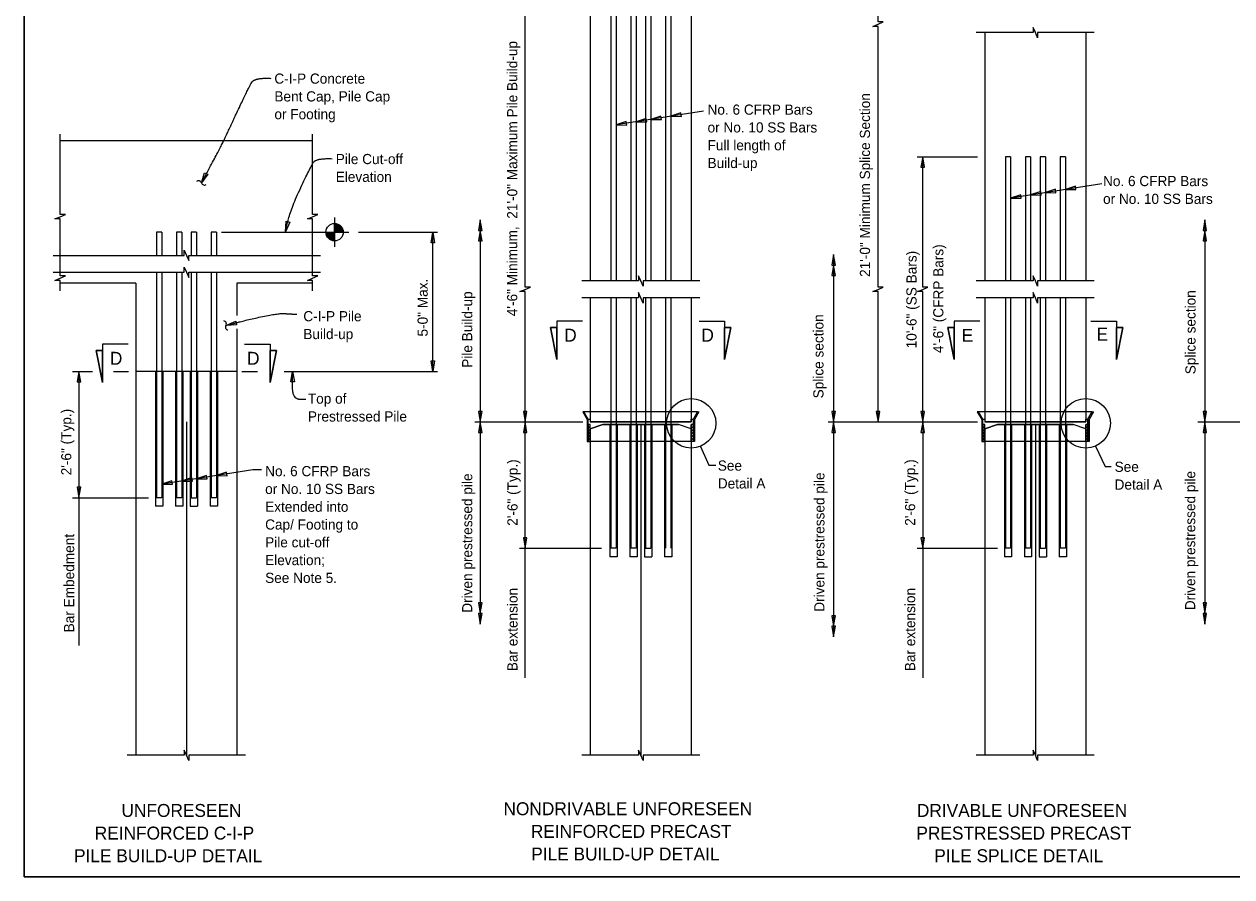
# Model space of a CAD drawing. Extents: x 0 to 41.1, y 0 to 25.9.
# Drawn here: x 0 to 23.92, y 0 to 16.88 of the extents above; entities that cross this region are included whole.
import ezdxf

# ---------------------------------------------------------------- set-up
doc = ezdxf.new("R2010")
doc.units = 0
for name, color, linetype in [('CL_Minor', 7, 'Continuous'), ('Dimension', 7, 'Continuous'), ('Miscellaneous', 7, 'Continuous'), ('Miscellaneous1', 7, 'Continuous'), ('PileConc', 7, 'Continuous'), ('PileConc_h', 7, 'Continuous'), ('Rebar', 7, 'Continuous'), ('Rebar_h', 7, 'Continuous'), ('SteelGirder', 7, 'Continuous'), ('SteelGirder_h', 7, 'Continuous'), ('Symbols', 7, 'Continuous'), ('TextStructures', 7, 'Continuous')]:
    doc.layers.add(name, color=color, linetype=linetype)

msp = doc.modelspace()

# ---------------------------------------------------------------- linework, layer by layer
at = {"layer": 'CL_Minor'}
for p, q in [((3.214, 9.004), (3.214, 2.407)), ((12.212, 8.942), (12.212, 2.407)), ((20.027, 8.942), (20.027, 2.407))]:
    msp.add_line(p, q, dxfattribs=at)
at = {"layer": 'Dimension'}
for p, q in [((13.454, 15.159), (11.723, 14.886)), ((17.687, 14.254), (18.882, 14.254)), ((21.342, 13.72), (19.538, 13.435)), ((6.148, 13.051), (6.148, 12.472)), ((9.033, 13.005), (9.033, 9.005)), ((23.383, 13.005), (23.383, 9.004)), ((3.908, 12.762), (6.432, 12.762)), ((6.619, 12.762), (8.188, 12.762)), ((8.094, 10.004), (8.094, 12.762)), ((16.031, 12.319), (16.031, 9.004)), ((10.553, 10.243), (10.426, 10.876)), ((10.426, 10.876), (10.553, 10.876)), ((11.059, 11.002), (10.553, 11.002)), ((10.553, 11.002), (10.553, 10.243)), ((13.366, 11.002), (13.872, 11.002)), ((13.872, 11.002), (13.872, 10.243)), ((13.872, 10.243), (13.998, 10.876)), ((13.998, 10.876), (13.872, 10.876)), ((18.422, 10.239), (18.295, 10.872)), ((18.295, 10.872), (18.422, 10.872)), ((18.928, 10.999), (18.422, 10.999)), ((18.422, 10.999), (18.422, 10.239)), ((21.127, 10.999), (21.633, 10.999)), ((21.633, 10.999), (21.633, 10.239)), ((21.633, 10.239), (21.759, 10.872)), ((21.759, 10.872), (21.633, 10.872)), ((2.06, 10.544), (1.554, 10.544)), ((1.554, 10.544), (1.554, 9.785)), ((4.367, 10.544), (4.873, 10.544)), ((4.873, 10.544), (4.873, 9.785)), ((1.554, 9.785), (1.428, 10.417)), ((1.428, 10.417), (1.554, 10.417)), ((4.873, 9.785), (5, 10.417)), ((5, 10.417), (4.873, 10.417)), ((0.96, 10.004), (1.351, 10.004)), ((1.085, 10.004), (1.085, 7.504)), ((1.77, 10.004), (2.068, 10.004)), ((4.314, 10.004), (4.619, 10.004)), ((5.149, 10.004), (8.188, 10.004)), ((8.923, 9.004), (11.067, 9.004)), ((9.033, 9.005), (9.033, 5.004)), ((15.921, 9.004), (18.882, 9.004)), ((16.031, 9.004), (16.031, 4.754)), ((17.797, 9.004), (17.797, 6.504)), ((23.246, 9.004), (26.46, 9.004)), ((23.383, 9.004), (23.383, 5.004)), ((13.394, 8.517), (13.56, 8.15)), ((21.216, 8.525), (21.408, 8.124)), ((13.56, 8.15), (13.699, 8.15)), ((4.528, 8.057), (2.724, 7.773)), ((4.703, 8.057), (4.528, 8.057)), ((21.408, 8.124), (21.53, 8.124)), ((0.96, 7.504), (2.462, 7.504)), ((1.085, 7.504), (1.085, 4.577)), ((9.812, 6.505), (11.436, 6.505)), ((17.687, 6.504), (19.276, 6.504)), ((17.797, 6.504), (17.797, 3.941))]:
    msp.add_line(p, q, dxfattribs=at)
for points in [[(0, 0), (41.051, 0), (41.051, 25.946), (0, 25.946)], [(12.806, 15.057), (13.017, 15.054), (13.007, 15.124)], [(11.723, 14.886), (11.934, 14.883), (11.923, 14.953)], [(12.119, 14.948), (12.33, 14.946), (12.319, 15.015)], [(12.41, 14.994), (12.622, 14.992), (12.611, 15.061)], [(17.797, 14.255), (17.762, 14.046), (17.832, 14.046)], [(3.635, 13.907), (3.511, 13.736), (3.572, 13.938)], [(20.621, 13.606), (20.832, 13.604), (20.821, 13.673)], [(19.538, 13.435), (19.749, 13.433), (19.738, 13.503)], [(19.934, 13.498), (20.145, 13.495), (20.134, 13.565)], [(20.225, 13.544), (20.436, 13.541), (20.426, 13.611)], [(5.261, 12.96), (5.173, 12.768), (5.192, 12.978)], [(9.033, 13.005), (8.997, 12.796), (9.068, 12.796)], [(23.383, 13.005), (23.348, 12.796), (23.419, 12.796)], [(8.059, 12.554), (8.094, 12.762), (8.129, 12.554)], [(9.033, 12.796), (8.997, 12.588), (9.068, 12.588)], [(23.383, 12.796), (23.348, 12.588), (23.419, 12.588)], [(16.031, 12.319), (15.996, 12.111), (16.067, 12.111)], [(16.031, 12.111), (15.996, 11.903), (16.067, 11.903)], [(4.206, 10.93), (3.995, 10.916), (4.19, 10.998)], [(10.553, 10.876), (10.426, 10.876), (10.553, 10.243)], [(13.872, 10.876), (13.998, 10.876), (13.872, 10.243)], [(18.422, 10.872), (18.295, 10.872), (18.422, 10.239)], [(21.633, 10.872), (21.759, 10.872), (21.633, 10.239)], [(1.554, 10.417), (1.428, 10.417), (1.554, 9.785)], [(4.873, 10.417), (5, 10.417), (4.873, 9.785)], [(8.129, 10.213), (8.094, 10.004), (8.059, 10.213)], [(1.085, 10.005), (1.05, 9.796), (1.121, 9.796)], [(5.281, 9.796), (5.316, 10.004), (5.352, 9.796)], [(9.033, 9.005), (9.068, 9.213), (8.997, 9.213)], [(9.922, 9.005), (9.958, 9.213), (9.887, 9.213)], [(16.031, 9.005), (16.067, 9.213), (15.996, 9.213)], [(16.911, 9.005), (16.947, 9.213), (16.876, 9.213)], [(17.797, 9.005), (17.832, 9.213), (17.762, 9.213)], [(23.383, 9.005), (23.419, 9.213), (23.348, 9.213)], [(9.033, 9.005), (8.997, 8.796), (9.068, 8.796)], [(9.922, 9.005), (9.887, 8.796), (9.958, 8.796)], [(16.031, 9.005), (15.996, 8.796), (16.067, 8.796)], [(17.797, 9.005), (17.762, 8.796), (17.832, 8.796)], [(23.383, 9.005), (23.348, 8.796), (23.419, 8.796)], [(3.12, 7.835), (3.331, 7.833), (3.32, 7.902)], [(3.412, 7.881), (3.623, 7.879), (3.612, 7.948)], [(3.808, 7.944), (4.019, 7.941), (4.008, 8.011)], [(1.085, 7.505), (1.121, 7.713), (1.05, 7.713)], [(2.724, 7.773), (2.935, 7.77), (2.924, 7.84)], [(9.922, 6.505), (9.958, 6.713), (9.887, 6.713)], [(17.797, 6.505), (17.832, 6.713), (17.762, 6.713)], [(9.033, 5.213), (9.068, 5.421), (8.997, 5.421)], [(23.383, 5.213), (23.419, 5.421), (23.348, 5.421)], [(9.033, 5.005), (9.068, 5.213), (8.997, 5.213)], [(16.031, 4.962), (16.067, 5.17), (15.996, 5.17)], [(23.383, 5.005), (23.419, 5.213), (23.348, 5.213)], [(16.031, 4.754), (16.067, 4.962), (15.996, 4.962)]]:
    msp.add_lwpolyline(points, close=True, dxfattribs=at)
for points in [[(9.922, 3.941), (9.922, 11.585), (9.819, 11.585), (9.922, 11.63), (10.026, 11.675), (9.922, 11.675), (9.922, 19.505)], [(16.911, 14.255), (16.911, 16.835), (16.808, 16.835), (16.911, 16.88), (17.015, 16.925), (16.911, 16.925), (16.911, 19.505)], [(21.195, 16.713), (20.072, 16.713), (20.072, 16.609), (20.027, 16.713), (19.982, 16.816), (19.982, 16.713), (18.856, 16.713)], [(0.714, 12.162), (0.714, 13.023), (0.61, 13.023), (0.714, 13.068), (0.817, 13.113), (0.714, 13.113), (0.714, 14.7)], [(5.714, 12.166), (5.714, 13.023), (5.61, 13.023), (5.714, 13.068), (5.817, 13.113), (5.714, 13.113), (5.714, 14.7)], [(16.911, 9.005), (16.911, 11.585), (16.808, 11.585), (16.911, 11.63), (17.015, 11.675), (16.911, 11.675), (16.911, 14.255)], [(17.797, 9.005), (17.797, 11.585), (17.694, 11.585), (17.797, 11.63), (17.901, 11.675), (17.797, 11.675), (17.797, 14.255)], [(0.577, 12.301), (3.169, 12.301), (3.169, 12.405), (3.214, 12.301), (3.259, 12.198), (3.259, 12.301), (5.867, 12.301)], [(0.577, 11.968), (3.169, 11.968), (3.169, 12.071), (3.214, 11.968), (3.259, 11.864), (3.259, 11.968), (5.867, 11.968)], [(0.714, 11.602), (0.714, 11.806), (0.61, 11.806), (0.714, 11.851), (0.817, 11.896), (0.714, 11.896), (0.714, 12.162)], [(5.714, 11.602), (5.714, 11.806), (5.61, 11.806), (5.714, 11.851), (5.817, 11.896), (5.714, 11.896), (5.714, 12.166)], [(13.38, 11.796), (12.257, 11.796), (12.257, 11.693), (12.212, 11.796), (12.167, 11.9), (12.167, 11.796), (11.042, 11.796)], [(21.195, 11.796), (20.072, 11.796), (20.072, 11.693), (20.027, 11.796), (19.982, 11.9), (19.982, 11.796), (18.856, 11.796)], [(13.38, 11.463), (12.257, 11.463), (12.257, 11.359), (12.212, 11.463), (12.167, 11.566), (12.167, 11.463), (11.042, 11.463)], [(21.195, 11.463), (20.072, 11.463), (20.072, 11.359), (20.027, 11.463), (19.982, 11.566), (19.982, 11.463), (18.856, 11.463)], [(4.381, 2.407), (3.259, 2.407), (3.259, 2.304), (3.214, 2.407), (3.169, 2.51), (3.169, 2.407), (2.043, 2.407)], [(13.38, 2.407), (12.257, 2.407), (12.257, 2.304), (12.212, 2.407), (12.167, 2.51), (12.167, 2.407), (11.042, 2.407)], [(21.195, 2.407), (20.072, 2.407), (20.072, 2.304), (20.027, 2.407), (19.982, 2.51), (19.982, 2.407), (18.856, 2.407)]]:
    msp.add_lwpolyline(points, dxfattribs=at)
for centre in [(13.211, 8.978), (21.026, 8.978)]:
    msp.add_circle(centre, 0.489, dxfattribs=at)
for centre, start, end in [((3.454, 13.718), 17.7163, 129.4435), ((3.568, 13.754), 197.7163, 309.4435), ((3.945, 10.948), 327.4852, 79.2124), ((4.045, 10.884), 147.4852, 259.2124)]:
    msp.add_arc(centre, 0.0596, start, end, dxfattribs=at)
for points in [[(3.511, 13.736), (3.869, 14.395), (4.069, 14.818), (4.452, 15.639), (4.568, 15.822), (4.885, 15.807)], [(5.173, 12.768), (5.17, 12.762), (5.284, 13.227), (5.668, 14.048), (5.784, 14.231), (6.101, 14.216)], [(3.995, 10.916), (3.992, 10.911), (4.401, 11.024), (5.053, 11.161), (5.274, 11.14), (5.403, 11.14)], [(5.316, 10.004), (5.314, 9.999), (5.302, 9.557), (5.41, 9.45), (5.57, 9.458), (5.576, 9.458)]]:
    msp.add_open_spline(points, degree=2, dxfattribs=at)
at = {"layer": 'Miscellaneous'}
for p, q in [((11.171, 8.942), (11.181, 8.952)), ((11.171, 8.883), (11.212, 8.924)), ((11.171, 8.824), (11.212, 8.865)), ((13.212, 8.942), (13.223, 8.952)), ((13.212, 8.883), (13.254, 8.924)), ((13.212, 8.824), (13.254, 8.865)), ((18.986, 8.942), (18.996, 8.952)), ((18.986, 8.883), (19.027, 8.924)), ((18.986, 8.824), (19.027, 8.865)), ((21.027, 8.942), (21.038, 8.952)), ((21.027, 8.883), (21.069, 8.924)), ((21.027, 8.824), (21.069, 8.865)), ((11.171, 8.765), (11.212, 8.806)), ((11.171, 8.706), (11.212, 8.747)), ((11.171, 8.647), (11.212, 8.688)), ((11.202, 8.619), (11.212, 8.629)), ((13.212, 8.765), (13.254, 8.806)), ((13.212, 8.706), (13.254, 8.747)), ((13.212, 8.647), (13.254, 8.688)), ((13.244, 8.619), (13.254, 8.629)), ((18.986, 8.765), (19.027, 8.806)), ((18.986, 8.706), (19.027, 8.747)), ((18.986, 8.647), (19.027, 8.688)), ((19.017, 8.619), (19.027, 8.629)), ((21.027, 8.765), (21.069, 8.806)), ((21.027, 8.706), (21.069, 8.747)), ((21.027, 8.647), (21.069, 8.688)), ((21.059, 8.619), (21.069, 8.629))]:
    msp.add_line(p, q, dxfattribs=at)
for points in [[(11.171, 9.057), (11.212, 9.057), (11.212, 9.004), (13.212, 9.004), (13.212, 9.057), (13.254, 9.057), (13.254, 8.952), (13.212, 8.952), (13.212, 8.869), (12.962, 8.952), (11.462, 8.952), (11.212, 8.869), (11.212, 8.952), (11.171, 8.952)], [(11.212, 8.952), (11.171, 8.952), (11.171, 8.619), (11.212, 8.619)], [(13.212, 8.952), (13.254, 8.952), (13.254, 8.619), (13.212, 8.619)], [(18.986, 9.057), (19.027, 9.057), (19.027, 9.004), (21.027, 9.004), (21.027, 9.057), (21.069, 9.057), (21.069, 8.952), (21.027, 8.952), (21.027, 8.869), (20.777, 8.952), (19.277, 8.952), (19.027, 8.869), (19.027, 8.952), (18.986, 8.952)], [(19.027, 8.952), (18.986, 8.952), (18.986, 8.619), (19.027, 8.619)], [(21.027, 8.952), (21.069, 8.952), (21.069, 8.619), (21.027, 8.619)]]:
    msp.add_lwpolyline(points, close=True, dxfattribs=at)
at = {"layer": 'Miscellaneous1'}
msp.add_lwpolyline([(0, 25.946), (41.051, 25.946), (41.051, 0), (0, 0)], close=True, dxfattribs=at)
at = {"layer": 'PileConc'}
for p, q in [((11.212, 19.504), (11.212, 11.796)), ((13.212, 19.504), (13.212, 11.796)), ((19.027, 16.713), (19.027, 11.796)), ((21.027, 16.713), (21.027, 11.796)), ((5.714, 14.568), (0.714, 14.568)), ((2.214, 11.749), (0.714, 11.749)), ((2.214, 11.749), (2.214, 9.004)), ((4.214, 11.749), (4.214, 11.111)), ((5.714, 11.749), (4.214, 11.749)), ((11.212, 11.463), (11.212, 9.004)), ((13.212, 11.463), (13.212, 9.004)), ((19.027, 11.463), (19.027, 9.004)), ((21.027, 11.463), (21.027, 9.004)), ((4.214, 10.846), (4.214, 9.004)), ((2.214, 9.004), (2.214, 2.407)), ((4.214, 9.004), (4.214, 2.407)), ((13.212, 9.004), (11.212, 9.004)), ((11.212, 8.869), (11.462, 8.952)), ((11.212, 8.869), (11.212, 2.407)), ((11.462, 8.952), (12.962, 8.952)), ((13.212, 8.869), (12.962, 8.952)), ((13.212, 8.869), (13.212, 2.407)), ((21.027, 9.004), (19.027, 9.004)), ((19.027, 8.869), (19.277, 8.952)), ((19.027, 8.869), (19.027, 2.407)), ((19.277, 8.952), (20.777, 8.952)), ((21.027, 8.869), (20.777, 8.952)), ((21.027, 8.869), (21.027, 2.407))]:
    msp.add_line(p, q, dxfattribs=at)
at = {"layer": 'PileConc_h'}
for p, q in [((4.214, 10.004), (2.214, 10.004)), ((2.599, 10.004), (2.599, 7.338)), ((2.745, 10.004), (2.745, 7.338)), ((2.995, 10.004), (2.995, 7.338)), ((3.141, 10.004), (3.141, 7.338)), ((3.286, 10.004), (3.286, 7.338)), ((3.432, 10.004), (3.432, 7.338)), ((3.682, 10.004), (3.682, 7.338)), ((3.828, 10.004), (3.828, 7.338)), ((11.598, 8.952), (11.598, 6.338)), ((11.744, 8.952), (11.744, 6.338)), ((11.994, 8.952), (11.994, 6.338)), ((12.14, 8.952), (12.14, 6.338)), ((12.285, 8.952), (12.285, 6.338)), ((12.431, 8.952), (12.431, 6.338)), ((12.681, 8.952), (12.681, 6.338)), ((12.827, 8.952), (12.827, 6.338)), ((19.413, 8.952), (19.413, 6.338)), ((19.558, 8.952), (19.558, 6.338)), ((19.809, 8.952), (19.809, 6.338)), ((19.954, 8.952), (19.954, 6.338)), ((20.1, 8.952), (20.1, 6.338)), ((20.246, 8.952), (20.246, 6.338)), ((20.496, 8.952), (20.496, 6.338)), ((20.642, 8.952), (20.642, 6.338)), ((2.745, 7.338), (2.599, 7.338)), ((3.141, 7.338), (2.995, 7.338)), ((3.286, 7.338), (3.432, 7.338)), ((3.828, 7.338), (3.682, 7.338)), ((11.744, 6.338), (11.598, 6.338)), ((12.14, 6.338), (11.994, 6.338)), ((12.285, 6.338), (12.431, 6.338)), ((12.827, 6.338), (12.681, 6.338)), ((19.558, 6.338), (19.413, 6.338)), ((19.954, 6.338), (19.809, 6.338)), ((20.1, 6.338), (20.246, 6.338)), ((20.642, 6.338), (20.496, 6.338))]:
    msp.add_line(p, q, dxfattribs=at)
at = {"layer": 'Rebar'}
for p, q in [((2.724, 7.504), (2.62, 7.504)), ((3.12, 7.504), (3.016, 7.504)), ((3.307, 7.504), (3.411, 7.504)), ((3.807, 7.504), (3.703, 7.504)), ((19.538, 6.504), (19.433, 6.504)), ((19.934, 6.504), (19.829, 6.504)), ((20.121, 6.504), (20.225, 6.504)), ((20.621, 6.504), (20.517, 6.504))]:
    msp.add_line(p, q, dxfattribs=at)
at = {"layer": 'Rebar_h'}
for p, q in [((11.619, 19.254), (11.619, 11.796)), ((11.723, 19.254), (11.723, 11.796)), ((12.015, 19.254), (12.015, 11.796)), ((12.119, 19.254), (12.119, 11.796)), ((12.306, 19.254), (12.306, 11.796)), ((12.41, 19.254), (12.41, 11.796)), ((12.702, 19.254), (12.702, 11.796)), ((12.806, 19.254), (12.806, 11.796)), ((19.538, 14.254), (19.433, 14.254)), ((19.433, 14.254), (19.433, 11.796)), ((19.538, 14.254), (19.538, 11.796)), ((19.934, 14.254), (19.829, 14.254)), ((19.829, 14.254), (19.829, 11.796)), ((19.934, 14.254), (19.934, 11.796)), ((20.225, 14.254), (20.121, 14.254)), ((20.121, 14.254), (20.121, 11.796)), ((20.225, 14.254), (20.225, 11.796)), ((20.621, 14.254), (20.517, 14.254)), ((20.517, 14.254), (20.517, 11.796)), ((20.621, 14.254), (20.621, 11.796)), ((2.724, 12.762), (2.62, 12.762)), ((2.62, 12.762), (2.62, 12.301)), ((2.724, 12.762), (2.724, 12.301)), ((3.12, 12.762), (3.016, 12.762)), ((3.016, 12.762), (3.016, 12.301)), ((3.12, 12.762), (3.12, 12.301)), ((3.411, 12.762), (3.307, 12.762)), ((3.307, 12.762), (3.307, 12.301)), ((3.411, 12.762), (3.411, 12.301)), ((3.807, 12.762), (3.703, 12.762)), ((3.703, 12.762), (3.703, 12.301)), ((3.807, 12.762), (3.807, 12.301)), ((2.62, 11.968), (2.62, 7.504)), ((2.724, 11.968), (2.724, 7.504)), ((3.016, 11.968), (3.016, 7.504)), ((3.12, 11.968), (3.12, 7.504)), ((3.307, 11.968), (3.307, 7.504)), ((3.411, 11.968), (3.411, 7.504)), ((3.703, 11.968), (3.703, 7.504)), ((3.807, 11.968), (3.807, 7.504)), ((11.619, 11.463), (11.619, 6.505)), ((11.723, 11.463), (11.723, 6.505)), ((12.015, 11.463), (12.015, 6.505)), ((12.119, 11.463), (12.119, 6.505)), ((12.306, 11.463), (12.306, 6.505)), ((12.41, 11.463), (12.41, 6.505)), ((12.702, 11.463), (12.702, 6.505)), ((12.806, 11.463), (12.806, 6.505)), ((19.433, 11.463), (19.433, 6.504)), ((19.538, 11.463), (19.538, 6.504)), ((19.829, 11.463), (19.829, 6.504)), ((19.934, 11.463), (19.934, 6.504)), ((20.121, 11.463), (20.121, 6.504)), ((20.225, 11.463), (20.225, 6.504)), ((20.517, 11.463), (20.517, 6.504)), ((20.621, 11.463), (20.621, 6.504)), ((11.723, 6.505), (11.619, 6.505)), ((12.119, 6.505), (12.015, 6.505)), ((12.306, 6.505), (12.41, 6.505))]:
    msp.add_line(p, q, dxfattribs=at)
at = {"layer": 'SteelGirder'}
for p, q in [((11.212, 9.202), (11.086, 9.202)), ((13.338, 9.202), (13.212, 9.202)), ((19.027, 9.202), (18.901, 9.202)), ((21.153, 9.202), (21.027, 9.202)), ((11.212, 8.619), (11.171, 8.619)), ((13.254, 8.619), (13.212, 8.619)), ((19.027, 8.619), (18.986, 8.619)), ((21.069, 8.619), (21.027, 8.619))]:
    msp.add_line(p, q, dxfattribs=at)
for points in [[(11.086, 9.202), (11.062, 9.202), (11.15, 9.051), (11.15, 8.619), (11.171, 8.619), (11.171, 9.057)], [(13.338, 9.202), (13.362, 9.202), (13.275, 9.051), (13.275, 8.619), (13.254, 8.619), (13.254, 9.057)], [(18.901, 9.202), (18.877, 9.202), (18.965, 9.051), (18.965, 8.619), (18.986, 8.619), (18.986, 9.057)], [(21.153, 9.202), (21.177, 9.202), (21.09, 9.051), (21.09, 8.619), (21.069, 8.619), (21.069, 9.057)]]:
    msp.add_lwpolyline(points, close=True, dxfattribs=at)
at = {"layer": 'SteelGirder_h'}
for p, q in [((13.212, 9.202), (11.212, 9.202)), ((21.027, 9.202), (19.027, 9.202)), ((13.212, 8.619), (11.212, 8.619)), ((21.027, 8.619), (19.027, 8.619))]:
    msp.add_line(p, q, dxfattribs=at)
at = {"layer": 'Symbols'}
for p, q in [((6.078, 12.606), (6.218, 12.919)), ((6.095, 12.599), (6.201, 12.926)), ((6.112, 12.594), (6.184, 12.93)), ((6.13, 12.592), (6.166, 12.933)), ((6.148, 12.591), (6.148, 12.934)), ((5.976, 12.762), (6.32, 12.762)), ((5.977, 12.744), (6.319, 12.78)), ((5.98, 12.727), (6.316, 12.798)), ((5.985, 12.709), (6.311, 12.815)), ((5.991, 12.693), (6.305, 12.832)), ((5.999, 12.676), (6.297, 12.848)), ((6.009, 12.661), (6.287, 12.863)), ((6.02, 12.647), (6.275, 12.877)), ((6.033, 12.635), (6.263, 12.89)), ((6.047, 12.623), (6.249, 12.901)), ((6.062, 12.614), (6.234, 12.911))]:
    msp.add_line(p, q, dxfattribs=at)
msp.add_circle((6.148, 12.762), 0.172, dxfattribs=at)

# ---------------------------------------------------------------- texts
at = {"layer": 'Dimension'}
for s, height, p in [('C-I-P Concrete', 0.2016, (4.956, 15.701)), ('Bent Cap, Pile Cap', 0.2016, (4.956, 15.349)), ('or Footing', 0.2016, (4.956, 14.997)), ('No. 6 CFRP Bars', 0.2016, (13.535, 15.087)), ('or No. 10 SS Bars', 0.2016, (13.535, 14.735)), ('Full length of', 0.2016, (13.535, 14.383)), ('Pile Cut-off', 0.2016, (6.171, 14.109)), ('Build-up', 0.2016, (13.535, 14.031)), ('Elevation', 0.2016, (6.171, 13.757)), ('No. 6 CFRP Bars', 0.2016, (21.368, 13.673)), ('or No. 10 SS Bars', 0.2016, (21.368, 13.321)), ('No. 6 CFRP Bars', 0.2016, (4.773, 7.93)), ('See', 0.2016, (13.738, 8.04)), ('See', 0.2016, (21.597, 8.017)), ('Detail A', 0.2016, (13.738, 7.688)), ('or No. 10 SS Bars', 0.2016, (4.773, 7.578)), ('Detail A', 0.2016, (21.597, 7.665)), ('Extended into', 0.2016, (4.773, 7.226)), ('Cap/ Footing to', 0.2016, (4.773, 6.874)), ('Pile cut-off', 0.2016, (4.773, 6.522)), ('Elevation;', 0.2016, (4.773, 6.17)), ('See Note 5.', 0.2016, (4.773, 5.818)), ('UNFORESEEN', 0.256, (1.927, 1.186)), ('NONDRIVABLE UNFORESEEN', 0.256, (9.493, 1.22)), ('DRIVABLE UNFORESEEN', 0.256, (17.681, 1.186)), ('REINFORCED C-I-P', 0.256, (1.398, 0.738)), ('REINFORCED PRECAST', 0.256, (10.035, 0.772)), ('PRESTRESSED PRECAST', 0.256, (17.671, 0.738)), ('PILE BUILD-UP DETAIL', 0.256, (0.988, 0.29)), ('PILE BUILD-UP DETAIL', 0.256, (10.043, 0.324)), ('PILE SPLICE DETAIL', 0.256, (18.025, 0.29))]:
    msp.add_text(s, height=height, dxfattribs=at).set_placement(p)
msp.add_text('5-0" Max.', height=0.2016, rotation=90, dxfattribs=at).set_placement((7.993, 10.696))
at = {"layer": 'TextStructures'}
for s, p in [('4\'-6" Minimum,  21\'-0" Maximum Pile Build-up', (9.767, 11.098)), ('21\'-0" Minimum Splice Section', (16.753, 11.876)), ('4\'-6" (CFRP Bars)', (18.206, 10.367)), ('10\'-6" (SS Bars)', (17.675, 10.462)), ('Pile Build-up', (8.875, 10.077)), ('Splice section', (23.2, 9.949)), ('Splice section', (15.831, 9.472)), ('2\'-6" (Typ.)', (0.935, 7.949)), ('2\'-6" (Typ.)', (9.772, 6.949)), ('2\'-6" (Typ.)', (17.647, 6.949)), ('Driven prestressed pile', (8.875, 5.228)), ('Driven prestressed pile', (15.85, 5.248)), ('Driven prestressed pile', (23.194, 5.278)), ('Bar Embedment', (0.991, 4.84)), ('Bar extension', (9.772, 4.071)), ('Bar extension', (17.647, 4.071))]:
    msp.add_text(s, height=0.2016, rotation=90, dxfattribs=at).set_placement(p)
for s, height, p in [('C-I-P Pile', 0.2016, (5.529, 10.998)), ('Build-up', 0.2016, (5.529, 10.645)), ('D', 0.256, (10.696, 10.595)), ('D', 0.256, (13.413, 10.595)), ('E', 0.256, (18.569, 10.591)), ('E', 0.256, (21.238, 10.615)), ('D', 0.256, (1.698, 10.137)), ('D', 0.256, (4.415, 10.137)), ('Top of', 0.2016, (5.619, 9.366)), ('Prestressed Pile', 0.2016, (5.619, 9.013))]:
    msp.add_text(s, height=height, dxfattribs=at).set_placement(p)

doc.saveas('drawing.dxf')
